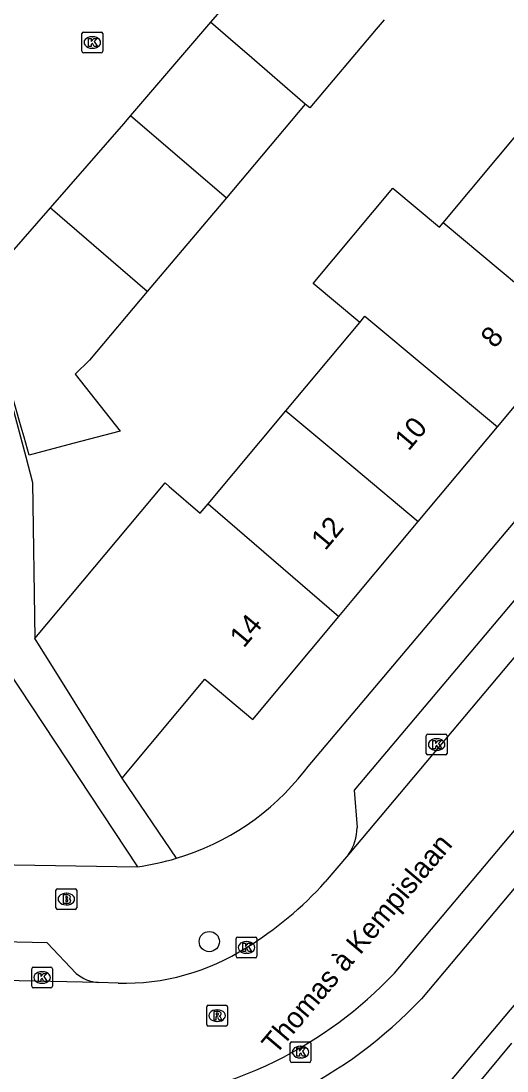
# Model space of a CAD drawing. Extents: x 162532 to 163264, y 381233 to 382042.
# Drawn here: x 162983.9 to 163007.4, y 381775.7 to 381826.4 of the extents above; entities that cross this region are included whole.
import ezdxf

# ---------------------------------------------------------------- set-up
doc = ezdxf.new("R2010")
doc.units = 0
for name, color, linetype in [('IMGEO_Boom', 7, 'Continuous'), ('IMGEO_Brandkraan', 7, 'Continuous'), ('IMGEO_Kolk', 7, 'Continuous'), ('IMGEO_Openbare_ruimte_label', 7, 'Continuous'), ('IMGEO_Pand', 7, 'Continuous'), ('IMGEO_Pand_nummerreeks', 7, 'Continuous'), ('IMGEO_Rijbaan_lokaal_open', 7, 'Continuous'), ('IMGEO_Rioolput', 7, 'Continuous'), ('IMGEO_Voetpad_open', 7, 'Continuous')]:
    doc.layers.add(name, color=color, linetype=linetype)

msp = doc.modelspace()

# ---------------------------------------------------------------- linework, layer by layer
at = {"layer": 'IMGEO_Boom'}
msp.add_circle((162993.027, 381781.952), 0.489, dxfattribs=at)
at = {"layer": 'IMGEO_Brandkraan'}
for p, q in [((162985.623, 381783.581), (162985.623, 381784.433)), ((162985.698, 381784.507), (162986.55, 381784.507)), ((162986.111, 381784.287), (162986.136, 381784.287)), ((162986.624, 381784.433), (162986.624, 381783.581)), ((162986.134, 381783.727), (162986.109, 381783.727)), ((162986.55, 381783.507), (162985.698, 381783.507))]:
    msp.add_line(p, q, dxfattribs=at)
for points in [[(162985.623, 381783.581), (162985.623, 381784.433)], [(162985.698, 381784.507), (162986.55, 381784.507)], [(162985.971, 381784.207), (162985.971, 381783.807), (162986.184, 381783.807)], [(162986.202, 381784.207), (162985.971, 381784.207)], [(162986.624, 381784.433), (162986.624, 381783.581)], [(162986.15, 381784.126), (162986.096, 381784.126), (162986.096, 381784.05)], [(162986.096, 381784.05), (162986.149, 381784.05)], [(162986.158, 381783.974), (162986.096, 381783.974), (162986.096, 381783.893)], [(162986.096, 381783.893), (162986.158, 381783.893)], [(162986.55, 381783.507), (162985.698, 381783.507)]]:
    msp.add_lwpolyline(points, dxfattribs=at)
for centre, radius, start, end in [((162985.7, 381784.431), 0.0765, 91.552, 178.448), ((162985.7, 381784.431), 0.0765, 91.552, 178.448), ((162986.206, 381784.062), 0.145, 59.4692, 91.5367), ((162986.548, 381784.431), 0.0765, 1.552, 88.448), ((162986.548, 381784.431), 0.0765, 1.552, 88.448), ((162986.151, 381784.088), 0.0379, 267.8285, 90.9355), ((162986.159, 381783.933), 0.0404, 269.8759, 90.5077), ((162986.19, 381784.058), 0.251, 268.6676, 293.5347), ((162986.231, 381784.109), 0.0922, 285.5137, 58.1501), ((162986.236, 381783.917), 0.105, 301.3115, 78.989), ((162985.7, 381783.583), 0.0765, 181.552, 268.448), ((162985.7, 381783.583), 0.0765, 181.552, 268.448), ((162986.548, 381783.583), 0.0765, 271.552, 358.448), ((162986.548, 381783.583), 0.0765, 271.552, 358.448)]:
    msp.add_arc(centre, radius, start, end, dxfattribs=at)
for centre, major_axis, ratio, start_param, end_param in [((162986.11, 381784.007), (-0.387, 0.002), 0.722429, 4.712389, 7.853982), ((162986.135, 381784.007), (-0.39, 0.002), 0.717154, 1.570796, 4.712389)]:
    msp.add_ellipse(centre, major_axis=major_axis, ratio=ratio, start_param=start_param, end_param=end_param, dxfattribs=at)
at = {"layer": 'IMGEO_Kolk'}
for p, q in [((162986.878, 381824.965), (162986.878, 381825.817)), ((162986.953, 381825.891), (162987.805, 381825.891)), ((162987.879, 381825.817), (162987.879, 381824.965)), ((162987.366, 381825.671), (162987.391, 381825.671)), ((162987.805, 381824.891), (162986.953, 381824.891)), ((162987.389, 381825.111), (162987.364, 381825.111)), ((163003.504, 381791.046), (163003.504, 381791.898)), ((163003.579, 381791.972), (163004.431, 381791.972)), ((163004.505, 381791.898), (163004.505, 381791.046)), ((163003.992, 381791.752), (163004.017, 381791.752)), ((163004.431, 381790.972), (163003.579, 381790.972)), ((163004.015, 381791.192), (163003.99, 381791.192)), ((162994.324, 381781.244), (162994.324, 381782.096)), ((162994.399, 381782.17), (162995.251, 381782.17)), ((162994.812, 381781.95), (162994.837, 381781.95)), ((162995.325, 381782.096), (162995.325, 381781.244)), ((162995.251, 381781.17), (162994.399, 381781.17)), ((162994.835, 381781.39), (162994.81, 381781.39)), ((162984.526, 381780.718), (162985.378, 381780.718)), ((162984.451, 381779.792), (162984.451, 381780.644)), ((162984.939, 381780.498), (162984.964, 381780.498)), ((162985.452, 381780.644), (162985.452, 381779.792)), ((162985.378, 381779.718), (162984.526, 381779.718)), ((162984.962, 381779.938), (162984.937, 381779.938)), ((162997.008, 381777.113), (162997.86, 381777.113)), ((162996.933, 381776.187), (162996.933, 381777.039)), ((162997.421, 381776.893), (162997.446, 381776.893)), ((162997.934, 381777.039), (162997.934, 381776.187)), ((162997.86, 381776.113), (162997.008, 381776.113)), ((162997.444, 381776.333), (162997.419, 381776.333))]:
    msp.add_line(p, q, dxfattribs=at)
for points in [[(162986.878, 381824.965), (162986.878, 381825.817)], [(162986.953, 381825.891), (162987.805, 381825.891)], [(162987.879, 381825.817), (162987.879, 381824.965)], [(162987.199, 381825.591), (162987.322, 381825.591), (162987.322, 381825.44), (162987.452, 381825.591), (162987.616, 381825.591), (162987.47, 381825.44), (162987.623, 381825.191), (162987.471, 381825.191), (162987.386, 381825.355), (162987.322, 381825.288), (162987.322, 381825.191), (162987.199, 381825.191), (162987.199, 381825.591)], [(162987.805, 381824.891), (162986.953, 381824.891)], [(163003.504, 381791.046), (163003.504, 381791.898)], [(163003.579, 381791.972), (163004.431, 381791.972)], [(163004.505, 381791.898), (163004.505, 381791.046)], [(163003.825, 381791.672), (163003.948, 381791.672), (163003.948, 381791.521), (163004.078, 381791.672), (163004.242, 381791.672), (163004.096, 381791.521), (163004.249, 381791.272), (163004.097, 381791.272), (163004.012, 381791.436), (163003.948, 381791.369), (163003.948, 381791.272), (163003.825, 381791.272), (163003.825, 381791.672)], [(163004.431, 381790.972), (163003.579, 381790.972)], [(162994.324, 381781.244), (162994.324, 381782.096)], [(162994.399, 381782.17), (162995.251, 381782.17)], [(162994.645, 381781.87), (162994.768, 381781.87), (162994.768, 381781.719), (162994.898, 381781.87), (162995.062, 381781.87), (162994.916, 381781.719), (162995.069, 381781.47), (162994.917, 381781.47), (162994.832, 381781.634), (162994.768, 381781.567), (162994.768, 381781.47), (162994.645, 381781.47), (162994.645, 381781.87)], [(162995.325, 381782.096), (162995.325, 381781.244)], [(162995.251, 381781.17), (162994.399, 381781.17)], [(162984.526, 381780.718), (162985.378, 381780.718)], [(162984.451, 381779.792), (162984.451, 381780.644)], [(162984.772, 381780.418), (162984.895, 381780.418), (162984.895, 381780.267), (162985.025, 381780.418), (162985.189, 381780.418), (162985.043, 381780.267), (162985.196, 381780.018), (162985.044, 381780.018), (162984.959, 381780.182), (162984.895, 381780.115), (162984.895, 381780.018), (162984.772, 381780.018), (162984.772, 381780.418)], [(162985.452, 381780.644), (162985.452, 381779.792)], [(162985.378, 381779.718), (162984.526, 381779.718)], [(162997.008, 381777.113), (162997.86, 381777.113)], [(162996.933, 381776.187), (162996.933, 381777.039)], [(162997.254, 381776.813), (162997.377, 381776.813), (162997.377, 381776.662), (162997.507, 381776.813), (162997.671, 381776.813), (162997.525, 381776.662), (162997.678, 381776.413), (162997.526, 381776.413), (162997.441, 381776.577), (162997.377, 381776.51), (162997.377, 381776.413), (162997.254, 381776.413), (162997.254, 381776.813)], [(162997.934, 381777.039), (162997.934, 381776.187)], [(162997.86, 381776.113), (162997.008, 381776.113)]]:
    msp.add_lwpolyline(points, dxfattribs=at)
for centre, start, end in [((162986.955, 381825.815), 91.552, 178.448), ((162986.955, 381825.815), 91.552, 178.448), ((162987.803, 381825.815), 1.552, 88.448), ((162987.803, 381825.815), 1.552, 88.448), ((162986.955, 381824.967), 181.552, 268.448), ((162986.955, 381824.967), 181.552, 268.448), ((162987.803, 381824.967), 271.552, 358.448), ((162987.803, 381824.967), 271.552, 358.448), ((163003.581, 381791.896), 91.552, 178.448), ((163003.581, 381791.896), 91.552, 178.448), ((163004.429, 381791.896), 1.552, 88.448), ((163004.429, 381791.896), 1.552, 88.448), ((163003.581, 381791.048), 181.552, 268.448), ((163003.581, 381791.048), 181.552, 268.448), ((163004.429, 381791.048), 271.552, 358.448), ((163004.429, 381791.048), 271.552, 358.448), ((162994.401, 381782.094), 91.552, 178.448), ((162994.401, 381782.094), 91.552, 178.448), ((162995.249, 381782.094), 1.552, 88.448), ((162995.249, 381782.094), 1.552, 88.448), ((162994.401, 381781.246), 181.552, 268.448), ((162994.401, 381781.246), 181.552, 268.448), ((162995.249, 381781.246), 271.552, 358.448), ((162995.249, 381781.246), 271.552, 358.448), ((162984.528, 381780.642), 91.552, 178.448), ((162984.528, 381780.642), 91.552, 178.448), ((162985.376, 381780.642), 1.552, 88.448), ((162985.376, 381780.642), 1.552, 88.448), ((162984.528, 381779.794), 181.552, 268.448), ((162984.528, 381779.794), 181.552, 268.448), ((162985.376, 381779.794), 271.552, 358.448), ((162985.376, 381779.794), 271.552, 358.448), ((162997.01, 381777.037), 91.552, 178.448), ((162997.01, 381777.037), 91.552, 178.448), ((162997.858, 381777.037), 1.552, 88.448), ((162997.858, 381777.037), 1.552, 88.448), ((162997.01, 381776.189), 181.552, 268.448), ((162997.01, 381776.189), 181.552, 268.448), ((162997.858, 381776.189), 271.552, 358.448), ((162997.858, 381776.189), 271.552, 358.448)]:
    msp.add_arc(centre, 0.0765, start, end, dxfattribs=at)
for centre, major_axis, ratio, start_param, end_param in [((162987.365, 381825.391), (-0.387, 0.002), 0.722429, 4.712389, 7.853982), ((162987.39, 381825.391), (-0.39, 0.002), 0.717154, 1.570796, 4.712389), ((163003.991, 381791.472), (-0.387, 0.002), 0.722429, 4.712389, 7.853982), ((163004.016, 381791.472), (-0.39, 0.002), 0.717154, 1.570796, 4.712389), ((162994.811, 381781.67), (-0.387, 0.002), 0.722429, 4.712389, 7.853982), ((162994.836, 381781.67), (-0.39, 0.002), 0.717154, 1.570796, 4.712389), ((162984.938, 381780.218), (-0.387, 0.002), 0.722429, 4.712389, 7.853982), ((162984.963, 381780.218), (-0.39, 0.002), 0.717154, 1.570796, 4.712389), ((162997.42, 381776.613), (-0.387, 0.002), 0.722429, 4.712389, 7.853982), ((162997.445, 381776.613), (-0.39, 0.002), 0.717154, 1.570796, 4.712389)]:
    msp.add_ellipse(centre, major_axis=major_axis, ratio=ratio, start_param=start_param, end_param=end_param, dxfattribs=at)
at = {"layer": 'IMGEO_Pand'}
for points in [[(162997.107, 381829.771), (162995.45, 381829.117), (162993.09, 381826.366)], [(162993.09, 381826.366), (162989.22, 381821.855)], [(162997.663, 381822.417), (162994.834, 381824.86), (162994.289, 381825.331), (162993.09, 381826.366)], [(163001.473, 381826.491), (163001.369, 381826.369), (163001.082, 381826.028), (162997.88, 381822.23), (162997.663, 381822.417)], [(162997.663, 381822.417), (162993.85, 381817.893)], [(162989.22, 381821.855), (162988.883, 381821.461), (162985.336, 381817.41)], [(162989.22, 381821.855), (162993.85, 381817.893)], [(163004.315, 381816.677), (163008.223, 381821.356)], [(163000.294, 381811.864), (162998.039, 381813.749), (163001.887, 381818.354), (163004.142, 381816.47), (163004.315, 381816.677)], [(162993.85, 381817.893), (162990.032, 381813.364)], [(162985.336, 381817.41), (162982.022, 381813.624)], [(162990.032, 381813.364), (162985.336, 381817.41)], [(163010.707, 381811.338), (163004.315, 381816.677)], [(162990.032, 381813.364), (162987.237, 381810.048), (162986.545, 381809.368), (162988.717, 381806.619), (162986.441, 381806.016), (162984.331, 381805.458), (162984.083, 381806.325), (162983.946, 381806.806), (162982.987, 381810.157), (162983.367, 381810.236)], [(163000.294, 381811.864), (163000.543, 381812.162), (163006.935, 381806.824)], [(162996.727, 381807.594), (163000.294, 381811.864)], [(163006.935, 381806.824), (163010.707, 381811.338)], [(162992.974, 381803.101), (162996.727, 381807.594)], [(162996.727, 381807.594), (163000, 381804.86), (163003.119, 381802.254)], [(163003.119, 381802.254), (163006.935, 381806.824)], [(162984.608, 381796.596), (162990.888, 381804.113), (162991.082, 381803.947), (162992.593, 381802.645), (162992.974, 381803.101)], [(162992.974, 381803.101), (162999.285, 381797.665)], [(162999.285, 381797.665), (163000, 381798.521), (163003.119, 381802.254)], [(162988.817, 381789.845), (162992.81, 381794.625), (162995.128, 381792.689), (162999.285, 381797.665)], [(162988.817, 381789.845), (162985.45, 381795.246), (162984.751, 381796.368), (162984.7, 381796.45), (162984.608, 381796.596)], [(163003.798, 381772.423), (163007.641, 381777.046)]]:
    msp.add_lwpolyline(points, dxfattribs=at)
at = {"layer": 'IMGEO_Rijbaan_lokaal_open'}
for points in [[(163009.427, 381797.675), (162999.743, 381786.166)], [(163001.963, 381780.42), (163013.045, 381793.607)], [(162999.743, 381786.166), (162998.625, 381784.833)], [(162987.671, 381779.97), (162954.65, 381780.67)], [(162988.621, 381779.946), (162987.671, 381779.97)]]:
    msp.add_lwpolyline(points, dxfattribs=at)
for centre, radius, start, end in [((162985.838, 381796.331), 17.197, 301.5078, 318.038), ((162988.931, 381790.855), 10.913, 268.3712, 302.6884), ((162987.004, 381794.642), 20.641, 296.5071, 316.4471), ((162988.835, 381790.903), 16.478, 267.867, 296.6102)]:
    msp.add_arc(centre, radius, start, end, dxfattribs=at)
at = {"layer": 'IMGEO_Rioolput'}
for p, q in [((162992.903, 381777.948), (162992.903, 381778.8)), ((162992.978, 381778.874), (162993.83, 381778.874)), ((162993.391, 381778.654), (162993.416, 381778.654)), ((162993.904, 381778.8), (162993.904, 381777.948)), ((162993.83, 381777.874), (162992.978, 381777.874)), ((162993.414, 381778.094), (162993.389, 381778.094))]:
    msp.add_line(p, q, dxfattribs=at)
for points in [[(162992.903, 381777.948), (162992.903, 381778.8)], [(162992.978, 381778.874), (162993.83, 381778.874)], [(162993.904, 381778.8), (162993.904, 381777.948)], [(162993.492, 381778.572), (162993.24, 381778.574), (162993.24, 381778.174)], [(162993.24, 381778.174), (162993.364, 381778.174), (162993.364, 381778.336), (162993.375, 381778.336)], [(162993.418, 381778.493), (162993.364, 381778.493), (162993.364, 381778.412)], [(162993.364, 381778.412), (162993.416, 381778.412)], [(162993.422, 381778.307), (162993.493, 381778.174), (162993.633, 381778.174), (162993.568, 381778.3)], [(162993.83, 381777.874), (162992.978, 381777.874)]]:
    msp.add_lwpolyline(points, dxfattribs=at)
for centre, radius, start, end in [((162992.98, 381778.798), 0.0765, 91.552, 178.448), ((162992.98, 381778.798), 0.0765, 91.552, 178.448), ((162993.828, 381778.798), 0.0765, 1.552, 88.448), ((162993.828, 381778.798), 0.0765, 1.552, 88.448), ((162993.374, 381778.283), 0.0533, 26.0293, 88.6989), ((162993.4, 381778.601), 0.19, 274.7715, 282.9687), ((162993.424, 381778.397), 0.0964, 77.0061, 93.1865), ((162993.438, 381778.454), 0.0378, 276.6634, 79.6772), ((162993.491, 381778.462), 0.109, 350.3612, 89.416), ((162993.489, 381778.462), 0.112, 277.5842, 350.9817), ((162993.473, 381778.247), 0.108, 29.5134, 73.7905), ((162992.98, 381777.95), 0.0765, 181.552, 268.448), ((162992.98, 381777.95), 0.0765, 181.552, 268.448), ((162993.828, 381777.95), 0.0765, 271.552, 358.448), ((162993.828, 381777.95), 0.0765, 271.552, 358.448)]:
    msp.add_arc(centre, radius, start, end, dxfattribs=at)
for centre, major_axis, ratio, start_param, end_param in [((162993.39, 381778.374), (-0.387, 0.002), 0.722429, 4.712389, 7.853982), ((162993.415, 381778.374), (-0.39, 0.002), 0.717154, 1.570796, 4.712389)]:
    msp.add_ellipse(centre, major_axis=major_axis, ratio=ratio, start_param=start_param, end_param=end_param, dxfattribs=at)
at = {"layer": 'IMGEO_Voetpad_open'}
for points in [[(162997.617, 381790.181), (162997.806, 381790.405), (163031.179, 381830.005)], [(163030.083, 381822.935), (163028.276, 381822.773), (163000.015, 381789.276), (163000.162, 381787.468)], [(162983.367, 381810.236), (162982.867, 381810.21), (162984.165, 381805.367), (162984.495, 381804.134), (162984.608, 381796.596)], [(162983.304, 381795.054), (162989.552, 381785.568)], [(163019.982, 381792.725), (163019.638, 381793.018), (163018.451, 381791.621), (162983.456, 381749.996), (162982.545, 381748.989), (162980.782, 381750.497), (162978.902, 381751.794)], [(163012.649, 381792.394), (163012.803, 381790.534), (163003.268, 381779.181)], [(162991.441, 381785.976), (162988.817, 381789.845)], [(162953.874, 381786.148), (162989.552, 381785.568)], [(162986.595, 381780.417), (162985.19, 381781.898), (162957.409, 381782.505), (162955.854, 381781.153)]]:
    msp.add_lwpolyline(points, dxfattribs=at)
for centre, radius, start, end in [((162987.902, 381797.812), 12.354, 286.6472, 321.8517), ((162997.979, 381787.452), 2.183, 323.9037, 0.4186), ((162987.9, 381797.792), 12.335, 277.6952, 286.6807), ((162987.835, 381781.883), 1.92, 229.7733, 265.108), ((162987.039, 381794.594), 22.381, 296.4779, 316.4776)]:
    msp.add_arc(centre, radius, start, end, dxfattribs=at)

# ---------------------------------------------------------------- texts
at = {"layer": 'IMGEO_Openbare_ruimte_label'}
msp.add_text('Thomas à Kempislaan', height=1, rotation=49.8276, dxfattribs=at).set_placement((162996.237, 381776.449))
at = {"layer": 'IMGEO_Pand_nummerreeks'}
for s, rotation, p in [('8', 49.9676, (163006.813, 381810.571)), ('10', 49.9676, (163002.651, 381805.616)), ('12', 50.1263, (162998.625, 381800.804)), ('14', 50.1281, (162994.69, 381796.096))]:
    msp.add_text(s, height=1, rotation=rotation, dxfattribs=at).set_placement(p)

doc.saveas('drawing.dxf')
